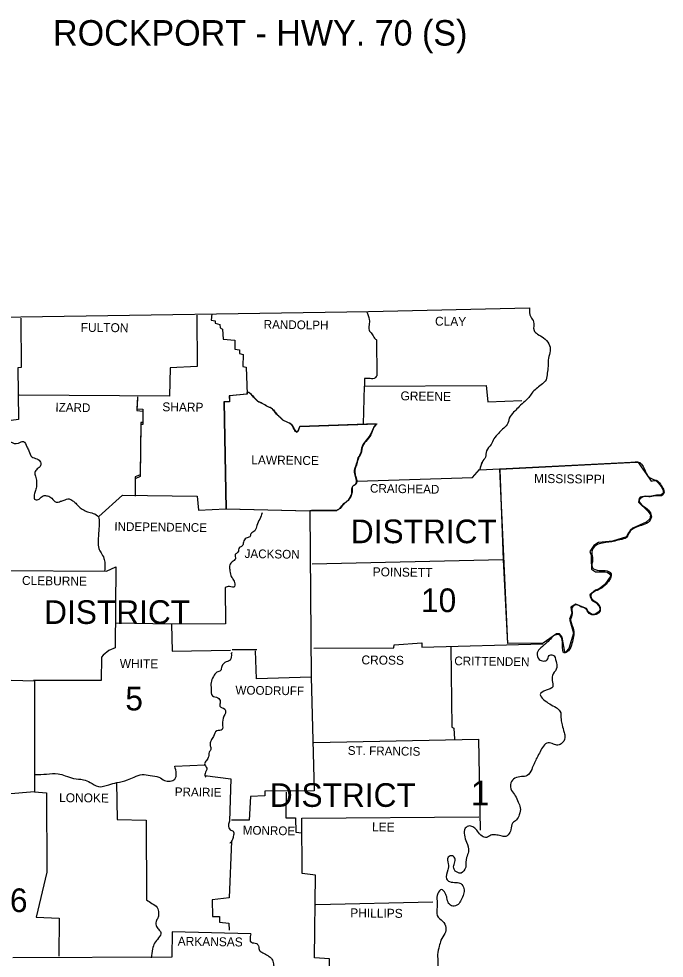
# Model space of a CAD drawing. Extents: x -984 to 3998, y 83 to 2143.
# Drawn here: x 2999.8 to 3303.9, y 1621.8 to 2064.9 of the extents above; entities that cross this region are included whole.
import ezdxf

# ---------------------------------------------------------------- set-up
doc = ezdxf.new("R2010")
doc.units = 0
for name, color, linetype in [('Level 1', 7, 'Continuous'), ('Level 2', 7, 'Continuous'), ('Level 3', 7, 'Continuous'), ('Level 42', 7, 'Continuous'), ('Level 45', 7, 'Continuous')]:
    doc.layers.add(name, color=color, linetype=linetype)

msp = doc.modelspace()

# ---------------------------------------------------------------- linework, layer by layer
at = {"layer": 'Level 1'}
for p, q in [((3162.68, 1895.2), (3162.68, 1891.58)), ((3108.28, 1888.64), (3107.18, 1888.61)), ((3130.69, 1869.95), (3131.63, 1870.88)), ((3168.15, 1873.86), (3132.15, 1872.59)), ((3161.99, 1873.56), (3162.17, 1873.74)), ((3216.98, 1852.15), (3218.15, 1855.77)), ((3217.27, 1853.32), (3218.45, 1856.16)), ((3226.44, 1852.5), (3290.81, 1855.67)), ((3230.26, 1770.24), (3226.44, 1852.5)), ((3290.81, 1855.67), (3291.37, 1855.7)), ((3291.37, 1855.7), (3291.82, 1855.38)), ((3291.82, 1855.38), (3293.06, 1853.59)), ((3293.06, 1853.59), (3295.41, 1850.21)), ((3295.41, 1850.21), (3297.76, 1846.83)), ((3297.76, 1846.83), (3298.93, 1847.15)), ((3298.93, 1847.15), (3300.13, 1846.95)), ((3300.13, 1846.95), (3301.22, 1845.84)), ((3301.22, 1845.84), (3302.44, 1844.22)), ((3302.44, 1844.22), (3303.37, 1842.41)), ((3292.54, 1839.21), (3292.13, 1838.66)), ((3295.05, 1839.76), (3292.54, 1839.21)), ((3297.13, 1839.52), (3295.05, 1839.76)), ((3300.28, 1840.15), (3297.13, 1839.52)), ((3302.17, 1840.17), (3300.28, 1840.15)), ((3303.38, 1841.03), (3302.17, 1840.17)), ((3303.37, 1842.41), (3303.38, 1841.03)), ((3292.13, 1838.66), (3291.68, 1836.86)), ((3291.68, 1836.86), (3296.38, 1832.49)), ((3296.38, 1832.49), (3297.46, 1830.89)), ((3297.46, 1830.89), (3297.04, 1829)), ((3295.44, 1827.39), (3289.06, 1824.56)), ((3297.04, 1829), (3295.44, 1827.39)), ((3286.65, 1822), (3286.16, 1820.57)), ((3287.8, 1823.5), (3286.65, 1822)), ((3289.06, 1824.56), (3287.8, 1823.5)), ((3272.94, 1817.78), (3270.72, 1816.36)), ((3279.52, 1818.48), (3272.94, 1817.78)), ((3286.16, 1820.57), (3279.52, 1818.48)), ((3270.72, 1816.36), (3268.77, 1813.6)), ((3268.77, 1813.6), (3269.38, 1811.81)), ((3269.38, 1811.81), (3269.38, 1809.93)), ((3269.38, 1809.93), (3269.56, 1805.26)), ((3269.56, 1805.26), (3271.52, 1804.08)), ((3271.52, 1804.08), (3273.82, 1804.01)), ((3273.82, 1804.01), (3276.11, 1803.94)), ((3276.11, 1803.94), (3276.94, 1803.91)), ((3276.94, 1803.91), (3278.02, 1803.11)), ((3278.67, 1802.05), (3275.86, 1798.05)), ((3278.02, 1803.11), (3278.67, 1802.05)), ((3271.5, 1795.32), (3268.87, 1793.19)), ((3273.22, 1796.05), (3271.5, 1795.32)), ((3275.86, 1798.05), (3273.22, 1796.05)), ((3268.87, 1793.19), (3268.96, 1792.19)), ((3268.96, 1792.19), (3269.77, 1790.66)), ((3269.77, 1790.66), (3271.69, 1789.6)), ((3262.17, 1788.78), (3259.84, 1787.28)), ((3259.84, 1787.28), (3259.96, 1786.15)), ((3259.96, 1786.15), (3260.3, 1784.47)), ((3264.4, 1787.87), (3262.17, 1788.78)), ((3267.29, 1786.68), (3264.4, 1787.87)), ((3268.24, 1784.93), (3267.29, 1786.68)), ((3271.69, 1789.6), (3273.18, 1787.81)), ((3273.69, 1786.39), (3273.11, 1785.14)), ((3273.18, 1787.81), (3273.69, 1786.39)), ((3260.3, 1784.47), (3259.31, 1781.64)), ((3259.31, 1781.64), (3261.05, 1775.14)), ((3269.98, 1783.95), (3268.24, 1784.93)), ((3271.38, 1784.01), (3269.98, 1783.95)), ((3273.11, 1785.14), (3271.38, 1784.01)), ((3253.09, 1774.83), (3246.81, 1770.36)), ((3254.51, 1774.73), (3253.09, 1774.83)), ((3255.79, 1773.15), (3254.51, 1774.73)), ((3257.01, 1766.05), (3255.79, 1773.15)), ((3261.05, 1775.14), (3258.99, 1767.82)), ((3246.81, 1770.36), (3230.26, 1770.24)), ((3100.35, 1767.42), (3112, 1767.42)), ((3257.56, 1766.24), (3257.01, 1766.05)), ((3258.99, 1767.82), (3257.56, 1766.24))]:
    msp.add_line(p, q, dxfattribs=at)
for points in [[(2703.71, 1924.06), (2861.92, 1923.96), (3000.75, 1924.25), (3164.54, 1926.8), (3240.46, 1928.56)], [(3000.75, 1923.67), (3000.95, 1900.38), (2999.28, 1900.28), (2999.58, 1875.92), (2992.73, 1874.94), (2993.32, 1868.39), (2995.66, 1865.35), (2995.47, 1857.63), (2982.16, 1857.14), (2981.67, 1845.2), (2969.54, 1844.81), (2968.95, 1830.33), (2969.64, 1829.15), (2969.93, 1806.06), (2990.87, 1804.69), (2990.58, 1753.13), (3007.21, 1752.64), (3007.21, 1700.2), (2994.1, 1699.22), (2993.12, 1687.68), (2971.11, 1687.58)], [(3083.62, 1925.14), (3083.82, 1900.87), (3071.1, 1900.19), (3070.71, 1886.88), (2999.97, 1887.27)], [(3090.74, 1925.65), (3090.37, 1922.69), (3092.33, 1922.4), (3092.23, 1921.22), (3094.48, 1920.73), (3094.68, 1919.17), (3095.75, 1918.48), (3096.05, 1913.79), (3101.63, 1913.2), (3101.63, 1908.99), (3103.68, 1908.7), (3103.68, 1907.03), (3105.44, 1906.55), (3105.34, 1900.87), (3106.91, 1900.58), (3107.3, 1887.76), (3098.98, 1886.98), (3099.08, 1884.24), (3096.54, 1884.14), (3097.42, 1833.65), (3136.85, 1832.77), (3137.53, 1754.31), (3111.8, 1753.62), (3111.31, 1766.83)], [(3168.35, 1913.39), (3168.45, 1896.47)], [(3107.18, 1888.61), (3107.2, 1887.76), (3098.89, 1886.98), (3098.98, 1884.24), (3096.44, 1884.14), (3097.32, 1833.65), (3136.75, 1832.77)], [(3162.16, 1873.64), (3162.68, 1891.58), (3162.68, 1891.58), (3219.91, 1891.87), (3220.7, 1884.24), (3236.84, 1884.82)], [(3055.64, 1886.59), (3055.44, 1880.91), (3058.18, 1880.72), (3058.28, 1874.45), (3057.3, 1874.45), (3056.91, 1849.8), (3054.66, 1848.82), (3054.66, 1840.6)], [(3055.64, 1885.71), (3055.44, 1880.03), (3058.18, 1879.84), (3058.28, 1873.57), (3057.3, 1873.57), (3056.91, 1848.92), (3054.66, 1847.94), (3054.66, 1839.72)], [(3132.25, 1872.59), (3168.55, 1873.87)], [(3168.16, 1873.77), (3168.15, 1873.86)], [(3159.25, 1846.76), (3213.55, 1848.53), (3216.78, 1852.24)], [(3216.98, 1852.15), (3291.24, 1855.96)], [(3226.37, 1852.05), (3228.04, 1809.68), (3229.99, 1770.25)], [(3037.44, 1830.13), (3048.6, 1840.21), (3083.82, 1839.72), (3084.5, 1833.17), (3097.32, 1833.65)], [(3136.75, 1832.77), (3137.63, 1832.97), (3149.57, 1832.97)], [(3149.67, 1832.97), (3137.73, 1832.97), (3136.85, 1832.77)], [(3228.04, 1809.68), (3137.92, 1807.63)], [(2990.87, 1804.69), (3041.16, 1804.4), (3045.46, 1806.45), (3045.17, 1768.2), (3042.24, 1766.93), (3039.59, 1764.68), (3038.71, 1763.8), (3038.62, 1752.84), (3006.62, 1752.84)], [(3096.93, 1796.67), (3097.12, 1779.45), (3071.69, 1779.35), (3045.56, 1779.84)], [(3071.69, 1779.35), (3072.08, 1766.54), (3099.57, 1767.02)], [(3138.71, 1768), (3176.47, 1768.2), (3176.57, 1769.57), (3189.68, 1770.55), (3189.68, 1768.49), (3246.63, 1770.06)], [(3203.38, 1768.49), (3203.87, 1730.82), (3204.75, 1730.24), (3205.04, 1725.15)], [(3100.35, 1765.75), (3099.86, 1765.66)], [(3137.53, 1754.31), (3139, 1700.69), (3115.71, 1700.59), (3115.62, 1698.44), (3108.87, 1698.05), (3108.28, 1686.89), (3100.06, 1686.89)], [(3138.71, 1723.49), (3216.39, 1725.05)], [(3216.39, 1725.05), (3217.18, 1682.2)], [(3073.25, 1712.33), (3087.44, 1713.02)], [(3087.44, 1707.93), (3099.67, 1706.36), (3098.98, 1686.4)], [(3045.86, 1704.7), (3046.05, 1687.19), (3059.85, 1686.89), (3059.95, 1649.32)], [(3007.21, 1700.2), (3012.88, 1699.81), (3012.98, 1662.43), (3007.89, 1641.2), (3018.75, 1640.71), (3018.66, 1622.71)], [(3125.69, 1700.1), (3125.6, 1687.97), (3130.1, 1687.97), (3130.29, 1681.22), (3133.13, 1680.93)], [(3138.71, 1601.18), (3146.34, 1601.67), (3146.24, 1621.54), (3139.1, 1622.02), (3139.49, 1660.87), (3133.33, 1661.75), (3133.13, 1687.87), (3216.59, 1688.46)], [(3100.06, 1677.01), (3098.89, 1650.2), (3090.86, 1649.32), (3091.06, 1641.4), (3094.29, 1641.5), (3094.39, 1638.76), (3098.79, 1638.27), (3098.89, 1635.04)], [(3139.69, 1647.07), (3194.87, 1648.44)], [(3109.06, 1633.28), (3072.08, 1634.26), (3071.88, 1622.22), (2997.03, 1621.93)]]:
    msp.add_lwpolyline(points, dxfattribs=at)
for points in [[(3240.46, 1928.56), (3240.95, 1924.25), (3242.32, 1922), (3242.52, 1917.9), (3244.18, 1916.13), (3247.02, 1914.37), (3249.56, 1911.54), (3250.15, 1908.21), (3249.36, 1904.78), (3249.17, 1900.97), (3248.78, 1897.64), (3248.19, 1894.61), (3245.84, 1892.16), (3243.59, 1890.4), (3241.54, 1888.35), (3240.07, 1886.19), (3237.53, 1883.85), (3234.98, 1881.4), (3232.93, 1879.25), (3230.87, 1876.51), (3229.89, 1873.48), (3227.64, 1871.32), (3225.88, 1869.37), (3223.53, 1866.72), (3222.36, 1864.08), (3220.11, 1861.05), (3219.62, 1858.11), (3218.15, 1855.77), (3218.06, 1855.37)], [(3163.59, 1926.79), (3164.93, 1923.08), (3164.83, 1920.44), (3164.83, 1917.99), (3166.1, 1916.33), (3167.37, 1914.28), (3168.35, 1913.39)], [(3168.45, 1896.47), (3167.18, 1895.2), (3164.73, 1895.2), (3162.68, 1895.2)], [(3132.15, 1872.59), (3130.59, 1869.95), (3129.12, 1872.01), (3128.04, 1873.67), (3124.81, 1875.24), (3122.76, 1876.9), (3120.7, 1878.95), (3119.24, 1880.81), (3116.99, 1881.99), (3114.44, 1883.46), (3112.29, 1884.53), (3110.43, 1886.39), (3108.28, 1888.64)], [(3108.38, 1888.64), (3110.53, 1886.39), (3112.39, 1884.53), (3114.54, 1883.46), (3117.08, 1881.99), (3119.33, 1880.81), (3120.8, 1878.95), (3122.86, 1876.9), (3124.91, 1875.24), (3128.14, 1873.67), (3129.22, 1872.01), (3130.68, 1869.95), (3132.25, 1872.59)], [(3149.57, 1832.97), (3151.03, 1833.95), (3152.99, 1836.2), (3154.85, 1837.67), (3156.12, 1839.62), (3156.71, 1841.58), (3157.1, 1844.42), (3158.57, 1845.49), (3158.76, 1847.74), (3158.08, 1850.19), (3158.08, 1852.64), (3158.96, 1854.98), (3159.74, 1857.72), (3161.11, 1860.46), (3161.41, 1862.52), (3163.17, 1865.55), (3165.52, 1868.68), (3166.69, 1871.42), (3168.16, 1873.77)], [(3168.25, 1873.77), (3166.79, 1871.42), (3165.61, 1868.68), (3163.26, 1865.55), (3161.5, 1862.52), (3161.21, 1860.46), (3159.84, 1857.72), (3159.06, 1854.98), (3158.18, 1852.64), (3158.18, 1850.19), (3158.86, 1847.74), (3158.67, 1845.49), (3157.2, 1844.42), (3156.81, 1841.58), (3156.22, 1839.62), (3154.95, 1837.67), (3153.09, 1836.2), (3151.13, 1833.95), (3149.67, 1832.97)], [(2995.66, 1865.35), (2999.58, 1864.67), (3001.93, 1865.55), (3003.59, 1863.01), (3004.47, 1861.05), (3005.94, 1858.21), (3008.29, 1857.33), (3010.05, 1855.77), (3010.05, 1854.1), (3008.48, 1852.54), (3007.31, 1850.97), (3007.7, 1849.11), (3008.09, 1846.57), (3008.09, 1844.12), (3007.5, 1841.87), (3007.01, 1839.82), (3007.5, 1838.06), (3009.36, 1838.35), (3011.32, 1839.82), (3013.37, 1839.82), (3015.33, 1838.74), (3017.38, 1836.88), (3019.44, 1837.27), (3021.1, 1837.76), (3023.45, 1838.45), (3025.11, 1837.57), (3026.58, 1836.39), (3028.34, 1834.53), (3030.01, 1833.36), (3032.16, 1832.28), (3034.8, 1831.6), (3037.25, 1829.94), (3037.64, 1827.1), (3037.54, 1824.65), (3037.34, 1821.62), (3037.15, 1818.29), (3037.44, 1815.06), (3038.52, 1812.91), (3039.89, 1810.37), (3040.28, 1808.02), (3040.18, 1804.3)], [(3290.16, 1855.86), (3291.24, 1855.96), (3294.57, 1852.44), (3296.03, 1849.5), (3298.19, 1847.84), (3300.63, 1846.96), (3302.49, 1844.71), (3303.76, 1842.26), (3303.08, 1840.11), (3300.34, 1839.92), (3297.31, 1839.43), (3294.37, 1839.52), (3292.02, 1837.57), (3294.18, 1834.93), (3297.01, 1832.48), (3297.8, 1829.84), (3296.23, 1827.29), (3293.1, 1825.92), (3290.07, 1824.75), (3287.33, 1822.4), (3286.05, 1820.15), (3283.02, 1819.17), (3279.89, 1818.29), (3277.15, 1818), (3274.02, 1817.41), (3270.99, 1815.95), (3269.72, 1813.4), (3270.11, 1809.78), (3270.01, 1805.97), (3273.24, 1804.69), (3276.08, 1804.6), (3278.81, 1803.13), (3278.52, 1800.98), (3276.47, 1798.24), (3274.02, 1796.08), (3271.57, 1795.01), (3269.32, 1792.95), (3270.11, 1790.9), (3272.16, 1789.53), (3273.63, 1787.28), (3273.43, 1785.22), (3271.09, 1783.76), (3268.54, 1784.34), (3266.68, 1786.79), (3264.53, 1787.57), (3262.67, 1788.45), (3260.52, 1787.18), (3260.52, 1784.34), (3259.74, 1781.31), (3260.42, 1779.06), (3261.3, 1775.93), (3261.2, 1773.58), (3260.42, 1770.25), (3258.76, 1766.83), (3256.8, 1765.75), (3256.02, 1769.47), (3255.63, 1772.5), (3254.45, 1774.27), (3252.89, 1774.36), (3250.83, 1772.9), (3248.58, 1770.64), (3245.74, 1768.2), (3244.08, 1765.75), (3244.96, 1762.72), (3247.11, 1761.94), (3248.78, 1762.52), (3249.66, 1764.48), (3251.32, 1764.77), (3252.89, 1761.74)], [(3114.44, 1831.89), (3113.27, 1828.86), (3111.9, 1825.92), (3111.02, 1823.38), (3109.16, 1821.91), (3108.57, 1820.54), (3106.91, 1819.96), (3105.64, 1818), (3105.05, 1816.24), (3103.68, 1815.46), (3103, 1813.3), (3101.72, 1812.13), (3101.82, 1810.17), (3100.35, 1808.8), (3099.18, 1807.24), (3099.18, 1805.08), (3099.67, 1802.25), (3100.65, 1800.58), (3101.53, 1798.43), (3101.43, 1797.06), (3098.98, 1797.06), (3096.93, 1796.67)], [(3099.86, 1765.66), (3099.37, 1762.43), (3097.52, 1761.55), (3095.36, 1759.39), (3094.87, 1757.44), (3093.11, 1756.65), (3091.45, 1754.6), (3090.37, 1751.76), (3090.37, 1748.83), (3091.06, 1745.5), (3093.5, 1744.62), (3094.68, 1742.66), (3094.48, 1740.61), (3096.83, 1739.24), (3097.22, 1738.06), (3096.83, 1736.79), (3095.75, 1733.17), (3095.85, 1730.73), (3095.66, 1729.65), (3093.02, 1728.96), (3091.45, 1726.32), (3090.37, 1724.46), (3089.98, 1722.02), (3090.28, 1720.26), (3089.49, 1718.89), (3089.2, 1716.83), (3088.22, 1715.07), (3087.34, 1713.41), (3088.32, 1711.45), (3088.03, 1710.08), (3087.44, 1707.93), (3087.93, 1707.24)], [(3252.89, 1761.74), (3253.28, 1758.9), (3251.62, 1755.87), (3251.03, 1752.84), (3251.32, 1749.8), (3248.19, 1748.14), (3245.45, 1746.18), (3247.02, 1743.84), (3249.95, 1741.68), (3252.89, 1740.02), (3254.75, 1738.36), (3255.24, 1734.35), (3255.72, 1731.8), (3256.7, 1728.28), (3257.09, 1725.83), (3255.33, 1722.9), (3253.28, 1722.31), (3251.13, 1723), (3248.58, 1723.19), (3246.53, 1721.24), (3245.06, 1718.5), (3243.59, 1715.76), (3242.52, 1713.41), (3241.44, 1710.86), (3239.29, 1707.93), (3236.65, 1707.44), (3233.51, 1706.66), (3231.66, 1704.5), (3231.95, 1700.88), (3233.71, 1698.44), (3235.08, 1695.41), (3236.06, 1692.76), (3235.57, 1689.44), (3234.2, 1686.99), (3232.44, 1685.52), (3231.66, 1682.39), (3230.38, 1680.04), (3229.21, 1679.26), (3226.86, 1679.46), (3224.32, 1679.95), (3222.16, 1679.75), (3220.11, 1678.67), (3218.06, 1679.36), (3215.9, 1681.71), (3214.14, 1683.47), (3212.19, 1684.15), (3210.13, 1683.08), (3209.74, 1679.85), (3210.72, 1676.52), (3211.6, 1672.02), (3210.72, 1669.28), (3210.42, 1664.78)], [(3007.4, 1708.42), (3012.88, 1708.61), (3018.26, 1708.81), (3021.69, 1707.83), (3025.6, 1706.56), (3030.2, 1705.97), (3033.43, 1704.7), (3037.25, 1702.74), (3042.14, 1703.62), (3045.95, 1704.6), (3050.94, 1705.87), (3054.17, 1707.24), (3057.89, 1708.42), (3061.61, 1707.93), (3065.82, 1707.15), (3068.46, 1705.58), (3073.25, 1706.27), (3073.25, 1712.33)], [(3098.98, 1686.4), (3098.59, 1684.45), (3099.37, 1682.39), (3100.74, 1681.71), (3100.94, 1679.75), (3100.45, 1677.79), (3100.06, 1677.01), (3099.18, 1675.84)], [(3210.42, 1664.78), (3208.17, 1661.94), (3204.85, 1663.71), (3204.85, 1666.05), (3205.34, 1668.5), (3204.16, 1670.06), (3202.11, 1669.38), (3202.11, 1666.35), (3201.91, 1663.41), (3201.32, 1659.2), (3202.69, 1657.93), (3205.83, 1657.54), (3208.08, 1656.95), (3209.45, 1654.7), (3209.35, 1651.96), (3208.27, 1649.32), (3206.71, 1647.17), (3204.26, 1646.39), (3202.3, 1647.66), (3201.52, 1650.2), (3200.64, 1652.45), (3198.98, 1654.12), (3197.22, 1652.26), (3196.82, 1648.83), (3196.92, 1645.9), (3196.92, 1641.89), (3199.47, 1639.24), (3201.03, 1636.21), (3200.54, 1633.47), (3198.68, 1630.24), (3197.9, 1627.41), (3197.12, 1623.59), (3197.22, 1619.38), (3196.53, 1615.27), (3195.16, 1612.53), (3192.62, 1610.28), (3190.95, 1608.82), (3189.58, 1607.35), (3188.9, 1604.41), (3188.41, 1602.36), (3186.55, 1599.91), (3185.08, 1599.72), (3183.91, 1600.7), (3183.52, 1602.36), (3183.52, 1604.02), (3182.74, 1605.69), (3180.29, 1606.37), (3178.33, 1606.27), (3177.45, 1604.9), (3178.72, 1601.09), (3179.21, 1598.64), (3178.53, 1595.31), (3178.92, 1594.92), (3175.4, 1593.06), (3172.56, 1592.77), (3170.21, 1592.09), (3167.96, 1590.62), (3166.88, 1588.47), (3165.32, 1586.7), (3163.95, 1585.04), (3162.09, 1584.26), (3160.04, 1584.65), (3157.3, 1584.94), (3155.73, 1582.99), (3156.22, 1580.15), (3158.08, 1578.49), (3160.82, 1577.7), (3163.66, 1577.9), (3166.4, 1578.19), (3168.94, 1576.82), (3168.45, 1574.18), (3166, 1572.91), (3162.38, 1572.52), (3159.45, 1572.81), (3155.93, 1572.03), (3154.17, 1569.78), (3155.14, 1566.35), (3158.96, 1564.98), (3160.72, 1561.76), (3160.82, 1558.72), (3159.55, 1554.71), (3157.79, 1552.85), (3154.36, 1552.07), (3151.72, 1551.58), (3151.33, 1547.08), (3150.15, 1544.83), (3148.1, 1544.14), (3145.16, 1545.61), (3143.4, 1546.3), (3141.25, 1547.27), (3138.51, 1548.94), (3136.46, 1548.64), (3137.04, 1544.34), (3137.24, 1544.14), (3139.59, 1540.92), (3141.94, 1538.37), (3143.01, 1535.34)], [(3059.95, 1649.32), (3062.39, 1647.66), (3064.93, 1645.7), (3065.62, 1643.06), (3065.42, 1641.2), (3064.64, 1639.64), (3064.45, 1637.19), (3065.62, 1635.43), (3066.7, 1633.96), (3065.62, 1631.32), (3063.76, 1628.87), (3062.78, 1626.13), (3062.1, 1622.02)], [(3109.06, 1633.28), (3109.35, 1629.27), (3111.7, 1628.68), (3112.68, 1627.6), (3113.17, 1625.35), (3114.83, 1624.37), (3117.08, 1623), (3118.45, 1622.02), (3119.43, 1620.46), (3120.02, 1617.92), (3121.58, 1616.25), (3123.74, 1615.47), (3125.3, 1613.61), (3126.28, 1610.97), (3127.85, 1609.79), (3129.41, 1607.74), (3130.19, 1606.86), (3131.56, 1604.51), (3132.93, 1603.34), (3133.91, 1602.65), (3135.48, 1602.16), (3137.43, 1600.89), (3138.71, 1598.93), (3138.71, 1597.47), (3138.22, 1595.22), (3137.83, 1592.87), (3137.63, 1590.23), (3137.43, 1587.88), (3138.32, 1585.92), (3137.83, 1582.99), (3136.85, 1581.42), (3136.75, 1579.27), (3136.46, 1576.04), (3136.07, 1574.18), (3135.18, 1571.15), (3133.91, 1569.58)]]:
    msp.add_spline(points, degree=3, dxfattribs=at)
at = {"layer": 'Level 45'}
msp.add_line((3108.38, 1888.64), (3107.27, 1888.61), dxfattribs=at)

# ---------------------------------------------------------------- texts
at = {"layer": 'Level 1'}
msp.add_text('1', height=11.74, dxfattribs=at).set_placement((3212.77, 1693.84))
at = {"layer": 'Level 2'}
for s, height, rotation, p in [('CLAY', 4.206, 359.2258, (3195.85, 1920.15)), ('FULTON', 4.206, 359.4996, (3028.93, 1917.21)), ('RANDOLPH', 4.109, 359.2583, (3115.13, 1918.68)), ('GREENE', 4.207, 359.2361, (3179.6, 1884.92)), ('IZARD', 4.108, 358.9258, (3016.99, 1879.64)), ('SHARP', 4.206, 359.3905, (3067.38, 1879.74)), ('LAWRENCE', 4.207, 359.2678, (3109.27, 1854.75)), ('MISSISSIPPI', 4.2062, 359.3097, (3242.52, 1845.98)), ('CRAIGHEAD', 4.109, 359.1159, (3165.22, 1841.38)), ('INDEPENDENCE', 4.1081, 359.2187, (3044.78, 1823.38)), ('JACKSON', 4.108, 359.1352, (3106.13, 1810.56)), ('POINSETT', 4.206, 359.1987, (3166.49, 1801.95)), ('CLEBURNE', 4.206, 359.2535, (3001.24, 1797.84)), ('CROSS', 4.206, 359.3839, (3161.21, 1760.37)), ('CRITTENDEN', 4.109, 359.213, (3204.94, 1759.98)), ('WHITE', 4.207, 359.3139, (3047.32, 1758.71)), ('WOODRUFF', 4.108, 359.2748, (3101.82, 1746.18)), ('ST. FRANCIS', 4.1081, 359.2216, (3154.75, 1717.71)), ('PRAIRIE', 4.109, 359.2116, (3073.25, 1698.24)), ('LONOKE', 4.207, 359.4974, (3018.75, 1695.41)), ('MONROE', 4.108, 359.0331, (3105.25, 1680.14)), ('LEE', 4.207, 359.4327, (3166.2, 1681.61)), ('PHILLIPS', 4.206, 359.3179, (3155.93, 1641.1)), ('ARKANSAS', 4.206, 359.2678, (3074.62, 1627.7))]:
    msp.add_text(s, height=height, rotation=rotation, dxfattribs=at).set_placement(p)
at = {"layer": 'Level 3'}
for s, height, p in [('DISTRICT', 11.154, (3156.22, 1817.51)), ('10', 11.154, (3189.29, 1785.03)), ('DISTRICT', 11.154, (3011.71, 1779.45)), ('5', 11.15, (3049.97, 1738.65)), ('DISTRICT', 11.154, (3118.06, 1693.16)), ('DISTRICT 6', 11.154, (2922.67, 1643.55))]:
    msp.add_text(s, height=height, dxfattribs=at).set_placement(p)
at = {"layer": 'Level 42'}
msp.add_text('ROCKPORT - HWY. 70 (S)', height=12, dxfattribs=at).set_placement((3015.9, 2052.22))

doc.saveas('drawing.dxf')
